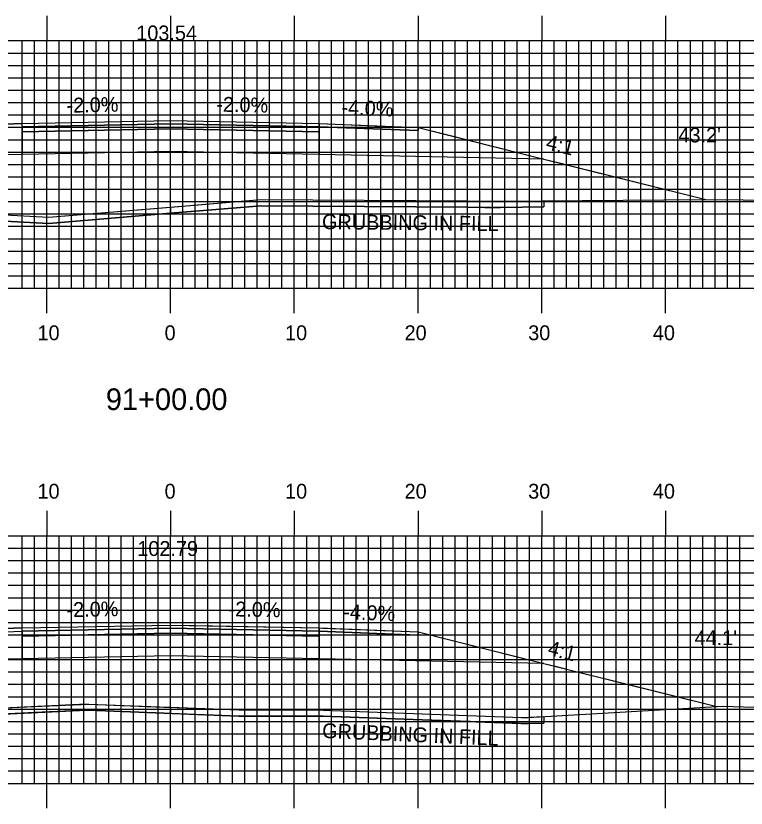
# Model space of a CAD drawing. Extents: x 1764546 to 1764889, y 442591 to 442811.
# Drawn here: x 1764698.8 to 1764757.9, y 442696.7 to 442760.7 of the extents above; entities that cross this region are included whole.
import ezdxf

# ---------------------------------------------------------------- set-up
doc = ezdxf.new("R2010")
doc.units = 0
for name, color, linetype in [('ANNOTATION', 7, 'Continuous'), ('D_Roadway_Centerline', 7, 'Continuous'), ('D_Roadway_Centerline_Text', 7, 'Continuous'), ('D_Roadway_Edge_Shoulder', 7, 'Continuous'), ('D_Roadway_Edge_TW', 7, 'Continuous'), ('D_Roadway_Pavement', 7, 'Continuous'), ('D_Roadway_SlopeLines', 7, 'Continuous'), ('D_Roadway_SubGrade', 7, 'Continuous'), ('D_Text_Standard', 7, 'Continuous'), ('GRUBBING IN FILL', 7, 'Continuous'), ('H_V ANNOTATION', 7, 'Continuous'), ('MAJOR', 7, 'Continuous'), ('MINOR', 7, 'Continuous'), ('S_Roadway_Centerline', 7, 'Continuous')]:
    doc.layers.add(name, color=color, linetype=linetype)

msp = doc.modelspace()

# ---------------------------------------------------------------- linework, layer by layer
at = {"layer": 'D_Roadway_Centerline'}
for points in [[(1764663.783, 442744.755), (1764663.79, 442744.757), (1764676.363, 442747.9), (1764681.169, 442749.102), (1764681.171, 442749.102), (1764681.173, 442749.103), (1764691.345, 442751.646), (1764699.345, 442751.966), (1764708.665, 442752.153), (1764711.345, 442752.206), (1764723.345, 442751.966), (1764723.348, 442751.966), (1764729.162, 442751.734), (1764731.343, 442751.646), (1764731.345, 442751.646), (1764733.645, 442751.071), (1764741.513, 442749.104), (1764741.519, 442749.102), (1764742.985, 442748.736), (1764743.345, 442748.646), (1764745.437, 442748.123), (1764754.594, 442745.833)], [(1764691.344, 442710.896), (1764691.344, 442710.896), (1764699.345, 442711.216), (1764711.345, 442711.456), (1764713.338, 442711.416), (1764723.345, 442711.216), (1764723.636, 442711.205), (1764731.345, 442710.896), (1764731.351, 442710.895), (1764739.47, 442708.865), (1764741.519, 442708.352), (1764742.426, 442708.126), (1764743.344, 442707.896), (1764743.346, 442707.896), (1764749.124, 442706.451), (1764755.477, 442704.863), (1764755.479, 442704.862)]]:
    msp.add_lwpolyline(points, dxfattribs=at)
at = {"layer": 'D_Roadway_Edge_Shoulder'}
for points in [[(1764699.345, 442751.966), (1764691.345, 442751.646), (1764691.345, 442751.396), (1764699.345, 442751.716)], [(1764723.345, 442751.966), (1764731.344, 442751.646), (1764731.344, 442751.396), (1764723.345, 442751.716)], [(1764699.345, 442711.216), (1764691.344, 442710.896), (1764691.344, 442710.646), (1764699.345, 442710.966)], [(1764723.345, 442711.216), (1764731.345, 442710.896), (1764731.345, 442710.646), (1764723.345, 442710.966)]]:
    msp.add_lwpolyline(points, close=True, dxfattribs=at)
at = {"layer": 'D_Roadway_Edge_TW'}
for points in [[(1764699.345, 442751.716), (1764699.345, 442751.966), (1764711.345, 442752.206), (1764723.345, 442751.966), (1764723.345, 442751.716), (1764711.345, 442751.956)], [(1764723.345, 442751.966), (1764723.345, 442751.966), (1764723.345, 442751.716), (1764723.345, 442751.716)], [(1764699.345, 442710.966), (1764699.345, 442711.216), (1764711.345, 442711.456), (1764723.345, 442711.216), (1764723.345, 442710.966), (1764711.345, 442711.206)], [(1764723.345, 442711.216), (1764723.345, 442711.216), (1764723.345, 442710.966), (1764723.345, 442710.966)]]:
    msp.add_lwpolyline(points, close=True, dxfattribs=at)
at = {"layer": 'D_Roadway_Pavement'}
for points in [[(1764699.345, 442751.299), (1764699.345, 442751.716), (1764711.345, 442751.956), (1764723.345, 442751.716), (1764723.345, 442751.299), (1764711.345, 442751.539)], [(1764723.345, 442751.716), (1764723.345, 442751.716), (1764723.345, 442751.299), (1764723.345, 442751.299)], [(1764699.345, 442710.549), (1764699.345, 442710.966), (1764711.345, 442711.206), (1764723.345, 442710.966), (1764723.345, 442710.549), (1764711.345, 442710.789)], [(1764723.345, 442710.966), (1764723.345, 442710.966), (1764723.345, 442710.549), (1764723.345, 442710.549)]]:
    msp.add_lwpolyline(points, close=True, dxfattribs=at)
for points in [[(1764723.345, 442751.716), (1764723.345, 442751.299)], [(1764723.345, 442751.716), (1764723.345, 442751.299)], [(1764723.345, 442751.716), (1764723.345, 442751.299)], [(1764723.345, 442710.966), (1764723.345, 442710.549)], [(1764723.345, 442710.966), (1764723.345, 442710.549)], [(1764723.345, 442710.966), (1764723.345, 442710.549)]]:
    msp.add_lwpolyline(points, dxfattribs=at)
at = {"layer": 'D_Roadway_SlopeLines'}
for points in [[(1764731.344, 442751.646), (1764741.518, 442749.102), (1764743.345, 442748.646), (1764754.593, 442745.833)], [(1764731.345, 442710.896), (1764741.519, 442708.352), (1764743.344, 442707.896), (1764755.479, 442704.862)]]:
    msp.add_lwpolyline(points, dxfattribs=at)
at = {"layer": 'D_Roadway_SubGrade'}
for points in [[(1764691.345, 442751.396), (1764699.345, 442751.716), (1764699.345, 442751.299), (1764699.345, 442749.466), (1764681.171, 442749.102), (1764691.345, 442751.646)], [(1764723.345, 442751.299), (1764723.345, 442751.716), (1764731.344, 442751.396), (1764731.344, 442751.646), (1764741.518, 442749.102), (1764723.345, 442749.466)], [(1764699.345, 442749.466), (1764699.345, 442751.299), (1764711.345, 442751.539), (1764723.345, 442751.299), (1764723.345, 442749.466), (1764711.345, 442749.706)], [(1764723.345, 442751.299), (1764723.345, 442751.299), (1764723.345, 442749.466), (1764723.345, 442749.466)], [(1764699.345, 442708.716), (1764699.345, 442710.549), (1764711.345, 442710.789), (1764723.345, 442710.549), (1764723.345, 442708.716), (1764711.345, 442708.956)], [(1764723.345, 442710.549), (1764723.345, 442710.966), (1764731.345, 442710.646), (1764731.345, 442710.896), (1764741.519, 442708.352), (1764723.345, 442708.716)], [(1764723.345, 442710.549), (1764723.345, 442710.549), (1764723.345, 442708.716), (1764723.345, 442708.716)]]:
    msp.add_lwpolyline(points, close=True, dxfattribs=at)
msp.add_lwpolyline([(1764691.344, 442710.896), (1764691.344, 442710.646), (1764699.345, 442710.966), (1764699.345, 442710.549), (1764699.345, 442708.716), (1764691.345, 442708.556)], dxfattribs=at)
at = {"layer": 'GRUBBING IN FILL'}
for p, q in [((1764741.518, 442745.727), (1764741.518, 442745.227)), ((1764741.519, 442704.057), (1764741.519, 442703.54))]:
    msp.add_line(p, q, dxfattribs=at)
for points in [[(1764681.171, 442744.591), (1764682.024, 442744.667), (1764693.34, 442744.337), (1764701.508, 442743.899), (1764711.339, 442744.715), (1764718.68, 442745.32), (1764735.325, 442745.213), (1764736.726, 442745.197), (1764737.998, 442745.198), (1764741.518, 442745.227)], [(1764681.171, 442703.956), (1764683.72, 442703.985), (1764687.072, 442703.964), (1764688.587, 442703.963), (1764690.76, 442704.039), (1764696.695, 442704.211), (1764703.998, 442704.555), (1764704.738, 442704.565), (1764716.868, 442704.101), (1764723.686, 442704.085), (1764739.686, 442703.492), (1764740.033, 442703.491), (1764740.216, 442703.491), (1764741.519, 442703.54)]]:
    msp.add_lwpolyline(points, dxfattribs=at)
for points in [[(1764711.345, 442745.217), (1764718.661, 442745.82), (1764726.996, 442745.767), (1764731.821, 442745.736), (1764735.33, 442745.713), (1764737.995, 442745.698), (1764741.518, 442745.727), (1764741.518, 442745.227), (1764737.998, 442745.198), (1764735.325, 442745.213), (1764727.003, 442745.267), (1764718.68, 442745.32), (1764711.339, 442744.715)], [(1764711.345, 442745.217), (1764718.661, 442745.82), (1764726.996, 442745.767), (1764731.821, 442745.736), (1764735.33, 442745.713), (1764737.995, 442745.698), (1764741.518, 442745.727), (1764741.518, 442745.227), (1764737.998, 442745.198), (1764735.325, 442745.213), (1764727.003, 442745.267), (1764718.68, 442745.32), (1764711.339, 442744.715)], [(1764681.171, 442745.093), (1764681.973, 442745.169), (1764687.666, 442745.003), (1764693.36, 442744.837), (1764701.5, 442744.4), (1764711.345, 442745.217), (1764711.345, 442744.716), (1764701.508, 442743.899), (1764697.424, 442744.118), (1764693.34, 442744.337), (1764687.682, 442744.502), (1764682.024, 442744.667), (1764681.171, 442744.591)], [(1764681.171, 442745.093), (1764681.973, 442745.169), (1764687.666, 442745.003), (1764693.36, 442744.837), (1764701.5, 442744.4), (1764711.345, 442745.217), (1764711.345, 442744.716), (1764701.508, 442743.899), (1764697.424, 442744.118), (1764693.34, 442744.337), (1764687.682, 442744.502), (1764682.024, 442744.667), (1764681.171, 442744.591)], [(1764681.171, 442703.956), (1764681.171, 442704.464), (1764683.719, 442704.485), (1764685.396, 442704.475), (1764688.579, 442704.463), (1764690.744, 442704.539), (1764693.71, 442704.625), (1764696.676, 442704.711), (1764700.33, 442704.883), (1764704.744, 442705.065), (1764710.811, 442704.833), (1764711.345, 442704.812), (1764711.345, 442704.312), (1764710.803, 442704.333), (1764704.738, 442704.565), (1764703.998, 442704.555), (1764700.347, 442704.383), (1764696.695, 442704.211), (1764693.728, 442704.125), (1764690.76, 442704.039), (1764688.587, 442703.963), (1764687.072, 442703.964), (1764683.72, 442703.985)], [(1764681.171, 442703.956), (1764681.171, 442704.464), (1764683.719, 442704.485), (1764685.396, 442704.475), (1764688.579, 442704.463), (1764690.744, 442704.539), (1764693.71, 442704.625), (1764696.676, 442704.711), (1764700.33, 442704.883), (1764704.744, 442705.065), (1764710.811, 442704.833), (1764711.345, 442704.812), (1764711.345, 442704.312), (1764710.803, 442704.333), (1764704.738, 442704.565), (1764703.998, 442704.555), (1764700.347, 442704.383), (1764696.695, 442704.211), (1764693.728, 442704.125), (1764690.76, 442704.039), (1764688.587, 442703.963), (1764687.072, 442703.964), (1764683.72, 442703.985)], [(1764711.345, 442704.812), (1764716.878, 442704.601), (1764720.287, 442704.593), (1764723.696, 442704.585), (1764731.696, 442704.289), (1764739.696, 442703.992), (1764741.519, 442704.057), (1764741.519, 442703.54), (1764740.216, 442703.491), (1764731.686, 442703.789), (1764723.686, 442704.085), (1764720.277, 442704.093), (1764716.868, 442704.101), (1764711.345, 442704.312)], [(1764711.345, 442704.812), (1764716.878, 442704.601), (1764720.287, 442704.593), (1764723.696, 442704.585), (1764731.696, 442704.289), (1764739.696, 442703.992), (1764741.519, 442704.057), (1764741.519, 442703.54), (1764740.216, 442703.491), (1764731.686, 442703.789), (1764723.686, 442704.085), (1764720.277, 442704.093), (1764716.868, 442704.101), (1764711.345, 442704.312)]]:
    msp.add_lwpolyline(points, close=True, dxfattribs=at)
at = {"layer": 'MAJOR'}
for p, q in [((1764701.345, 442760.669), (1764701.345, 442758.665)), ((1764711.345, 442760.669), (1764711.345, 442758.665)), ((1764721.345, 442760.669), (1764721.345, 442758.665)), ((1764731.345, 442760.669), (1764731.345, 442758.665)), ((1764741.345, 442760.669), (1764741.345, 442758.665)), ((1764751.345, 442760.669), (1764751.345, 442758.665)), ((1764571.345, 442758.665), (1764851.345, 442758.665)), ((1764571.345, 442758.665), (1764851.345, 442758.665)), ((1764701.345, 442738.665), (1764701.345, 442758.665)), ((1764711.345, 442738.665), (1764711.345, 442758.665)), ((1764721.345, 442738.665), (1764721.345, 442758.665)), ((1764731.345, 442738.665), (1764731.345, 442758.665)), ((1764741.345, 442738.665), (1764741.345, 442758.665)), ((1764751.345, 442738.665), (1764751.345, 442758.665)), ((1764571.345, 442753.665), (1764851.345, 442753.665)), ((1764571.345, 442748.665), (1764851.345, 442748.665)), ((1764571.345, 442743.665), (1764851.345, 442743.665)), ((1764571.345, 442738.665), (1764851.345, 442738.665)), ((1764571.345, 442738.665), (1764851.345, 442738.665)), ((1764701.345, 442736.661), (1764701.345, 442738.665)), ((1764711.345, 442736.661), (1764711.345, 442738.665)), ((1764721.345, 442736.661), (1764721.345, 442738.665)), ((1764731.345, 442736.661), (1764731.345, 442738.665)), ((1764741.345, 442736.661), (1764741.345, 442738.665)), ((1764751.345, 442736.661), (1764751.345, 442738.665)), ((1764701.345, 442720.669), (1764701.345, 442718.665)), ((1764711.345, 442720.669), (1764711.345, 442718.665)), ((1764721.345, 442720.669), (1764721.345, 442718.665)), ((1764731.345, 442720.669), (1764731.345, 442718.665)), ((1764741.345, 442720.669), (1764741.345, 442718.665)), ((1764751.345, 442720.669), (1764751.345, 442718.665)), ((1764571.345, 442718.665), (1764851.345, 442718.665)), ((1764571.345, 442718.665), (1764851.345, 442718.665)), ((1764701.345, 442698.665), (1764701.345, 442718.665)), ((1764711.345, 442698.665), (1764711.345, 442718.665)), ((1764721.345, 442698.665), (1764721.345, 442718.665)), ((1764731.345, 442698.665), (1764731.345, 442718.665)), ((1764741.345, 442698.665), (1764741.345, 442718.665)), ((1764751.345, 442698.665), (1764751.345, 442718.665)), ((1764571.345, 442713.665), (1764851.345, 442713.665)), ((1764571.345, 442708.665), (1764851.345, 442708.665)), ((1764571.345, 442703.665), (1764851.345, 442703.665)), ((1764571.345, 442698.665), (1764851.345, 442698.665)), ((1764571.345, 442698.665), (1764851.345, 442698.665)), ((1764701.345, 442696.661), (1764701.345, 442698.665)), ((1764711.345, 442696.661), (1764711.345, 442698.665)), ((1764721.345, 442696.661), (1764721.345, 442698.665)), ((1764731.345, 442696.661), (1764731.345, 442698.665)), ((1764741.345, 442696.661), (1764741.345, 442698.665)), ((1764751.345, 442696.661), (1764751.345, 442698.665))]:
    msp.add_line(p, q, dxfattribs=at)
at = {"layer": 'MINOR'}
for p, q in [((1764699.345, 442738.665), (1764699.345, 442758.665)), ((1764700.345, 442738.665), (1764700.345, 442758.665)), ((1764702.345, 442738.665), (1764702.345, 442758.665)), ((1764703.345, 442738.665), (1764703.345, 442758.665)), ((1764704.345, 442738.665), (1764704.345, 442758.665)), ((1764705.345, 442738.665), (1764705.345, 442758.665)), ((1764706.345, 442738.665), (1764706.345, 442758.665)), ((1764707.345, 442738.665), (1764707.345, 442758.665)), ((1764708.345, 442738.665), (1764708.345, 442758.665)), ((1764709.345, 442738.665), (1764709.345, 442758.665)), ((1764710.345, 442738.665), (1764710.345, 442758.665)), ((1764712.345, 442738.665), (1764712.345, 442758.665)), ((1764713.345, 442738.665), (1764713.345, 442758.665)), ((1764714.345, 442738.665), (1764714.345, 442758.665)), ((1764715.345, 442738.665), (1764715.345, 442758.665)), ((1764716.345, 442738.665), (1764716.345, 442758.665)), ((1764717.345, 442738.665), (1764717.345, 442758.665)), ((1764718.345, 442738.665), (1764718.345, 442758.665)), ((1764719.345, 442738.665), (1764719.345, 442758.665)), ((1764720.345, 442738.665), (1764720.345, 442758.665)), ((1764722.345, 442738.665), (1764722.345, 442758.665)), ((1764723.345, 442738.665), (1764723.345, 442758.665)), ((1764724.345, 442738.665), (1764724.345, 442758.665)), ((1764725.345, 442738.665), (1764725.345, 442758.665)), ((1764726.345, 442738.665), (1764726.345, 442758.665)), ((1764727.345, 442738.665), (1764727.345, 442758.665)), ((1764728.345, 442738.665), (1764728.345, 442758.665)), ((1764729.345, 442738.665), (1764729.345, 442758.665)), ((1764730.345, 442738.665), (1764730.345, 442758.665)), ((1764732.345, 442738.665), (1764732.345, 442758.665)), ((1764733.345, 442738.665), (1764733.345, 442758.665)), ((1764734.345, 442738.665), (1764734.345, 442758.665)), ((1764735.345, 442738.665), (1764735.345, 442758.665)), ((1764736.345, 442738.665), (1764736.345, 442758.665)), ((1764737.345, 442738.665), (1764737.345, 442758.665)), ((1764738.345, 442738.665), (1764738.345, 442758.665)), ((1764739.345, 442738.665), (1764739.345, 442758.665)), ((1764740.345, 442738.665), (1764740.345, 442758.665)), ((1764742.345, 442738.665), (1764742.345, 442758.665)), ((1764743.345, 442738.665), (1764743.345, 442758.665)), ((1764744.345, 442738.665), (1764744.345, 442758.665)), ((1764745.345, 442738.665), (1764745.345, 442758.665)), ((1764746.345, 442738.665), (1764746.345, 442758.665)), ((1764747.345, 442738.665), (1764747.345, 442758.665)), ((1764748.345, 442738.665), (1764748.345, 442758.665)), ((1764749.345, 442738.665), (1764749.345, 442758.665)), ((1764750.345, 442738.665), (1764750.345, 442758.665)), ((1764752.345, 442738.665), (1764752.345, 442758.665)), ((1764753.345, 442738.665), (1764753.345, 442758.665)), ((1764754.345, 442738.665), (1764754.345, 442758.665)), ((1764755.345, 442738.665), (1764755.345, 442758.665)), ((1764756.345, 442738.665), (1764756.345, 442758.665)), ((1764757.345, 442738.665), (1764757.345, 442758.665)), ((1764571.345, 442757.665), (1764851.345, 442757.665)), ((1764571.345, 442756.665), (1764851.345, 442756.665)), ((1764571.345, 442755.665), (1764851.345, 442755.665)), ((1764571.345, 442754.665), (1764851.345, 442754.665)), ((1764571.345, 442752.665), (1764851.345, 442752.665)), ((1764571.345, 442751.665), (1764851.345, 442751.665)), ((1764571.345, 442750.665), (1764851.345, 442750.665)), ((1764571.345, 442749.665), (1764851.345, 442749.665)), ((1764571.345, 442747.665), (1764851.345, 442747.665)), ((1764571.345, 442746.665), (1764851.345, 442746.665)), ((1764571.345, 442745.665), (1764851.345, 442745.665)), ((1764571.345, 442744.665), (1764851.345, 442744.665)), ((1764571.345, 442742.665), (1764851.345, 442742.665)), ((1764571.345, 442741.665), (1764851.345, 442741.665)), ((1764571.345, 442740.665), (1764851.345, 442740.665)), ((1764571.345, 442739.665), (1764851.345, 442739.665)), ((1764699.345, 442698.665), (1764699.345, 442718.665)), ((1764700.345, 442698.665), (1764700.345, 442718.665)), ((1764702.345, 442698.665), (1764702.345, 442718.665)), ((1764703.345, 442698.665), (1764703.345, 442718.665)), ((1764704.345, 442698.665), (1764704.345, 442718.665)), ((1764705.345, 442698.665), (1764705.345, 442718.665)), ((1764706.345, 442698.665), (1764706.345, 442718.665)), ((1764707.345, 442698.665), (1764707.345, 442718.665)), ((1764708.345, 442698.665), (1764708.345, 442718.665)), ((1764709.345, 442698.665), (1764709.345, 442718.665)), ((1764710.345, 442698.665), (1764710.345, 442718.665)), ((1764712.345, 442698.665), (1764712.345, 442718.665)), ((1764713.345, 442698.665), (1764713.345, 442718.665)), ((1764714.345, 442698.665), (1764714.345, 442718.665)), ((1764715.345, 442698.665), (1764715.345, 442718.665)), ((1764716.345, 442698.665), (1764716.345, 442718.665)), ((1764717.345, 442698.665), (1764717.345, 442718.665)), ((1764718.345, 442698.665), (1764718.345, 442718.665)), ((1764719.345, 442698.665), (1764719.345, 442718.665)), ((1764720.345, 442698.665), (1764720.345, 442718.665)), ((1764722.345, 442698.665), (1764722.345, 442718.665)), ((1764723.345, 442698.665), (1764723.345, 442718.665)), ((1764724.345, 442698.665), (1764724.345, 442718.665)), ((1764725.345, 442698.665), (1764725.345, 442718.665)), ((1764726.345, 442698.665), (1764726.345, 442718.665)), ((1764727.345, 442698.665), (1764727.345, 442718.665)), ((1764728.345, 442698.665), (1764728.345, 442718.665)), ((1764729.345, 442698.665), (1764729.345, 442718.665)), ((1764730.345, 442698.665), (1764730.345, 442718.665)), ((1764732.345, 442698.665), (1764732.345, 442718.665)), ((1764733.345, 442698.665), (1764733.345, 442718.665)), ((1764734.345, 442698.665), (1764734.345, 442718.665)), ((1764735.345, 442698.665), (1764735.345, 442718.665)), ((1764736.345, 442698.665), (1764736.345, 442718.665)), ((1764737.345, 442698.665), (1764737.345, 442718.665)), ((1764738.345, 442698.665), (1764738.345, 442718.665)), ((1764739.345, 442698.665), (1764739.345, 442718.665)), ((1764740.345, 442698.665), (1764740.345, 442718.665)), ((1764742.345, 442698.665), (1764742.345, 442718.665)), ((1764743.345, 442698.665), (1764743.345, 442718.665)), ((1764744.345, 442698.665), (1764744.345, 442718.665)), ((1764745.345, 442698.665), (1764745.345, 442718.665)), ((1764746.345, 442698.665), (1764746.345, 442718.665)), ((1764747.345, 442698.665), (1764747.345, 442718.665)), ((1764748.345, 442698.665), (1764748.345, 442718.665)), ((1764749.345, 442698.665), (1764749.345, 442718.665)), ((1764750.345, 442698.665), (1764750.345, 442718.665)), ((1764752.345, 442698.665), (1764752.345, 442718.665)), ((1764753.345, 442698.665), (1764753.345, 442718.665)), ((1764754.345, 442698.665), (1764754.345, 442718.665)), ((1764755.345, 442698.665), (1764755.345, 442718.665)), ((1764756.345, 442698.665), (1764756.345, 442718.665)), ((1764757.345, 442698.665), (1764757.345, 442718.665)), ((1764571.345, 442717.665), (1764851.345, 442717.665)), ((1764571.345, 442716.665), (1764851.345, 442716.665)), ((1764571.345, 442715.665), (1764851.345, 442715.665)), ((1764571.345, 442714.665), (1764851.345, 442714.665)), ((1764571.345, 442712.665), (1764851.345, 442712.665)), ((1764571.345, 442711.665), (1764851.345, 442711.665)), ((1764571.345, 442710.665), (1764851.345, 442710.665)), ((1764571.345, 442709.665), (1764851.345, 442709.665)), ((1764571.345, 442707.665), (1764851.345, 442707.665)), ((1764571.345, 442706.665), (1764851.345, 442706.665)), ((1764571.345, 442705.665), (1764851.345, 442705.665)), ((1764571.345, 442704.665), (1764851.345, 442704.665)), ((1764571.345, 442702.665), (1764851.345, 442702.665)), ((1764571.345, 442701.665), (1764851.345, 442701.665)), ((1764571.345, 442700.665), (1764851.345, 442700.665)), ((1764571.345, 442699.665), (1764851.345, 442699.665))]:
    msp.add_line(p, q, dxfattribs=at)
at = {"layer": 'S_Roadway_Centerline'}
for points in [[(1764649.258, 442744.752), (1764653.503, 442744.733), (1764661.66, 442744.749), (1764665.332, 442744.759), (1764671.902, 442744.778), (1764672.63, 442744.776), (1764675.11, 442744.853), (1764679.93, 442744.977), (1764681.973, 442745.169), (1764693.36, 442744.837), (1764701.5, 442744.4), (1764711.298, 442745.213), (1764718.661, 442745.82), (1764735.33, 442745.713), (1764736.729, 442745.697), (1764737.995, 442745.698), (1764754.509, 442745.834), (1764760.706, 442745.784)], [(1764651.219, 442705.013), (1764661.44, 442704.811), (1764666.687, 442704.702), (1764669.021, 442704.705), (1764670.588, 442704.622), (1764681.727, 442704.456), (1764682.014, 442704.466), (1764683.719, 442704.485), (1764687.074, 442704.464), (1764688.579, 442704.463), (1764690.744, 442704.539), (1764696.676, 442704.711), (1764703.983, 442705.055), (1764704.744, 442705.065), (1764716.878, 442704.601), (1764723.696, 442704.585), (1764739.696, 442703.992), (1764740.035, 442703.991), (1764740.207, 442703.991), (1764740.709, 442704.01), (1764755.963, 442704.89), (1764758.482, 442704.826)]]:
    msp.add_lwpolyline(points, dxfattribs=at)

# ---------------------------------------------------------------- texts
at = {"layer": 'ANNOTATION'}
for s, rotation, p in [('-2.0%', 1.14574, (1764702.951, 442752.839)), ('-2.0%', 358.85417, (1764715.031, 442752.933)), ('-4.0%', 357.70929, (1764725.138, 442752.696)), ('4:1', 345.96113, (1764741.604, 442749.92)), ('-2.0%', 1.14574, (1764702.951, 442712.089)), ('-2.0%', 358.85426, (1764716.028, 442712.163)), ('-4.0%', 357.70936, (1764725.282, 442711.94)), ('4:1', 345.96114, (1764741.754, 442709.056))]:
    msp.add_text(s, height=1.2, rotation=rotation, dxfattribs=at).set_placement(p)
at = {"layer": 'D_Roadway_Centerline'}
for s, p in [('C', (1764711.34, 442752.206)), ('L', (1764711.345, 442752.199)), ('C', (1764711.34, 442711.456)), ('L', (1764711.345, 442711.449))]:
    msp.add_text(s, height=0.0146, dxfattribs=at).set_placement(p)
at = {"layer": 'D_Roadway_Centerline_Text'}
for s, p in [('103.54', (1764708.573, 442758.687)), ('102.79', (1764708.658, 442717.036))]:
    msp.add_text(s, height=1.2, dxfattribs=at).set_placement(p)
at = {"layer": 'D_Text_Standard'}
for s, p in [("43.2'", (1764752.383, 442750.443)), ("44.1'", (1764753.687, 442709.83))]:
    msp.add_text(s, height=1.2, dxfattribs=at).set_placement(p)
at = {"layer": 'GRUBBING IN FILL'}
for rotation, p in [(359.35531, (1764723.58, 442743.442)), (357.46863, (1764723.573, 442702.336))]:
    msp.add_text('GRUBBING IN FILL', height=1.2, rotation=rotation, dxfattribs=at).set_placement(p)
at = {"layer": 'H_V ANNOTATION'}
for s, height, p in [('10', 1.2, (1764700.595, 442734.465)), ('0', 1.2, (1764710.863, 442734.465)), ('10', 1.2, (1764720.595, 442734.465)), ('20', 1.2, (1764730.253, 442734.465)), ('30', 1.2, (1764740.242, 442734.465)), ('40', 1.2, (1764750.317, 442734.465)), ('91+00.00', 1.75, (1764706.117, 442728.821)), ('10', 1.2, (1764700.595, 442721.665)), ('0', 1.2, (1764710.863, 442721.665)), ('10', 1.2, (1764720.595, 442721.665)), ('20', 1.2, (1764730.253, 442721.665)), ('30', 1.2, (1764740.242, 442721.665)), ('40', 1.2, (1764750.317, 442721.665))]:
    msp.add_text(s, height=height, dxfattribs=at).set_placement(p)

doc.saveas('drawing.dxf')
